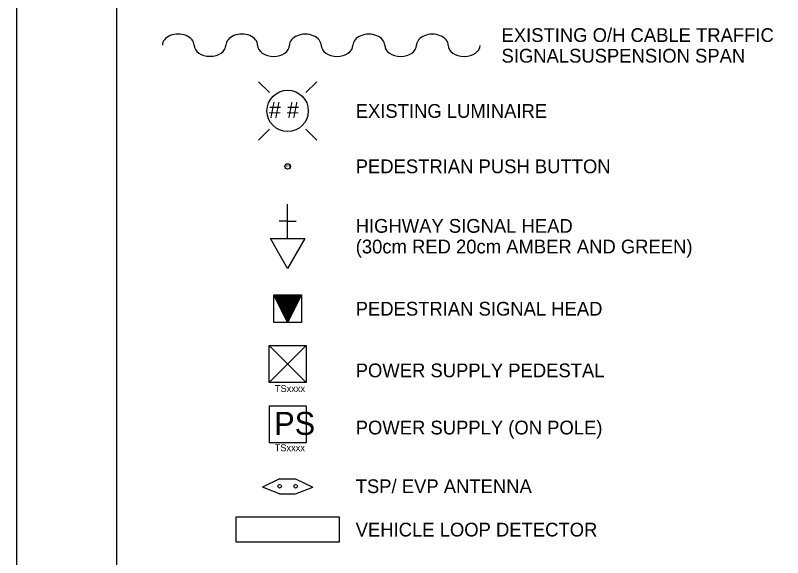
# Model space of a CAD drawing. Extents: x 595568 to 603392, y 4837996 to 4846579.
# Drawn here: x 603056.6 to 603080.76, y 4846502.21 to 4846519.3 of the extents above; entities that cross this region are included whole.
import ezdxf

# ---------------------------------------------------------------- set-up
doc = ezdxf.new("R2010")
doc.units = 0
for name, color, linetype in [('-PRINT HALFSIZE', 7, 'Continuous'), ('ENG_BORDER', 7, 'Continuous'), ('TCS_LEGEND', 7, 'Continuous'), ('TCS_LOOP', 7, 'Continuous'), ('TCS_LUMINAIRE-EXIST', 7, 'Continuous'), ('TCS_POWER', 7, 'Continuous'), ('TCS_PUSHBUTTON', 7, 'Continuous'), ('TCS_SIGNALHEAD', 7, 'Continuous'), ('TCS_SPAN-EXIST', 7, 'Continuous'), ('TCS_TSP-EVP', 7, 'Continuous')]:
    doc.layers.add(name, color=color, linetype=linetype)

msp = doc.modelspace()

# ---------------------------------------------------------------- linework, layer by layer
at = {"layer": '-PRINT HALFSIZE'}
msp.add_lwpolyline([(603056.659, 4846536.385), (603261.877, 4846536.304), (603261.821, 4846396.201), (603056.604, 4846396.282)], close=True, dxfattribs=at)
at = {"layer": 'ENG_BORDER'}
msp.add_lwpolyline([(603059.791, 4846533.885), (603059.791, 4846399.391)], dxfattribs=at)
at = {"layer": 'TCS_LOOP'}
msp.add_lwpolyline([(603063.549, 4846502.701), (603066.803, 4846502.701), (603066.803, 4846503.481), (603063.549, 4846503.481)], close=True, dxfattribs=at)
at = {"layer": 'TCS_LUMINAIRE-EXIST'}
for p, q in [((603064.601, 4846516.86), (603064.256, 4846517.205)), ((603065.751, 4846516.86), (603066.096, 4846517.205)), ((603064.601, 4846515.71), (603064.256, 4846515.365)), ((603065.751, 4846515.71), (603066.096, 4846515.365))]:
    msp.add_line(p, q, dxfattribs=at)
msp.add_circle((603065.176, 4846516.285), 0.651, dxfattribs=at)
at = {"layer": 'TCS_POWER'}
for p, q in [((603064.59, 4846508.897), (603065.762, 4846508.897)), ((603064.59, 4846507.726), (603064.59, 4846508.897)), ((603064.59, 4846508.897), (603065.762, 4846507.726)), ((603064.59, 4846507.726), (603065.762, 4846508.897)), ((603065.762, 4846508.897), (603065.762, 4846507.726)), ((603065.762, 4846507.726), (603064.59, 4846507.726)), ((603064.598, 4846506.995), (603064.598, 4846505.826)), ((603064.598, 4846506.995), (603065.754, 4846506.995)), ((603065.754, 4846506.995), (603065.754, 4846505.826)), ((603065.754, 4846505.826), (603064.598, 4846505.826))]:
    msp.add_line(p, q, dxfattribs=at)
at = {"layer": 'TCS_PUSHBUTTON'}
msp.add_circle((603065.176, 4846514.534), 0.0867, dxfattribs=at)
at = {"layer": 'TCS_SIGNALHEAD'}
for p, q in [((603065.176, 4846512.263), (603065.176, 4846513.351)), ((603065.176, 4846512.807), (603064.904, 4846512.807)), ((603065.176, 4846512.807), (603065.448, 4846512.807)), ((603065.176, 4846511.321), (603064.632, 4846512.263)), ((603064.632, 4846512.263), (603065.72, 4846512.263)), ((603065.72, 4846512.263), (603065.176, 4846511.321)), ((603064.742, 4846509.617), (603064.742, 4846510.484)), ((603064.745, 4846510.478), (603064.752, 4846510.484)), ((603064.752, 4846510.464), (603064.772, 4846510.484)), ((603064.759, 4846510.451), (603064.793, 4846510.484)), ((603064.766, 4846510.437), (603064.813, 4846510.484)), ((603064.773, 4846510.423), (603064.834, 4846510.484)), ((603064.78, 4846510.41), (603064.854, 4846510.484)), ((603064.786, 4846510.396), (603064.875, 4846510.484)), ((603064.793, 4846510.383), (603064.895, 4846510.484)), ((603064.8, 4846510.369), (603064.916, 4846510.484)), ((603064.807, 4846510.355), (603064.936, 4846510.484)), ((603064.814, 4846510.342), (603064.956, 4846510.484)), ((603064.82, 4846510.328), (603064.977, 4846510.484)), ((603064.827, 4846510.314), (603064.997, 4846510.484)), ((603064.834, 4846510.301), (603065.018, 4846510.484)), ((603064.841, 4846510.287), (603065.038, 4846510.484)), ((603064.848, 4846510.274), (603065.059, 4846510.484)), ((603064.855, 4846510.26), (603065.079, 4846510.484)), ((603064.861, 4846510.246), (603065.1, 4846510.484)), ((603064.868, 4846510.233), (603065.12, 4846510.484)), ((603064.875, 4846510.219), (603065.14, 4846510.484)), ((603064.882, 4846510.205), (603065.161, 4846510.484)), ((603064.889, 4846510.192), (603065.181, 4846510.484)), ((603064.895, 4846510.178), (603065.202, 4846510.484)), ((603064.902, 4846510.164), (603065.222, 4846510.484)), ((603064.909, 4846510.151), (603065.243, 4846510.484)), ((603064.916, 4846510.137), (603065.263, 4846510.484)), ((603064.923, 4846510.124), (603065.284, 4846510.484)), ((603064.93, 4846510.11), (603065.304, 4846510.484)), ((603064.936, 4846510.096), (603065.324, 4846510.484)), ((603064.943, 4846510.083), (603065.345, 4846510.484)), ((603064.95, 4846510.069), (603065.365, 4846510.484)), ((603064.957, 4846510.055), (603065.386, 4846510.484)), ((603064.964, 4846510.042), (603065.406, 4846510.484)), ((603064.97, 4846510.028), (603065.427, 4846510.484)), ((603064.977, 4846510.015), (603065.447, 4846510.484)), ((603064.984, 4846510.001), (603065.468, 4846510.484)), ((603064.991, 4846509.987), (603065.488, 4846510.484)), ((603064.998, 4846509.974), (603065.508, 4846510.484)), ((603065.004, 4846509.96), (603065.529, 4846510.484)), ((603065.011, 4846509.946), (603065.549, 4846510.484)), ((603065.018, 4846509.933), (603065.57, 4846510.484)), ((603065.025, 4846509.919), (603065.59, 4846510.484)), ((603065.032, 4846509.905), (603065.609, 4846510.483)), ((603065.039, 4846509.892), (603065.588, 4846510.442)), ((603065.045, 4846509.878), (603065.568, 4846510.401)), ((603065.052, 4846509.865), (603065.547, 4846510.36)), ((603065.059, 4846509.851), (603065.527, 4846510.319)), ((603065.066, 4846509.837), (603065.507, 4846510.278)), ((603065.61, 4846510.484), (603065.61, 4846509.617)), ((603065.073, 4846509.824), (603065.486, 4846510.237)), ((603065.079, 4846509.81), (603065.466, 4846510.196)), ((603065.086, 4846509.796), (603065.445, 4846510.155)), ((603065.093, 4846509.783), (603065.425, 4846510.115)), ((603065.1, 4846509.769), (603065.404, 4846510.074)), ((603065.107, 4846509.756), (603065.384, 4846510.033)), ((603065.114, 4846509.742), (603065.363, 4846509.992)), ((603065.12, 4846509.728), (603065.343, 4846509.951)), ((603065.127, 4846509.715), (603065.323, 4846509.91)), ((603065.134, 4846509.701), (603065.302, 4846509.869)), ((603065.141, 4846509.687), (603065.282, 4846509.828)), ((603065.61, 4846509.617), (603064.742, 4846509.617)), ((603065.148, 4846509.674), (603065.261, 4846509.787)), ((603065.154, 4846509.66), (603065.241, 4846509.746)), ((603065.161, 4846509.646), (603065.22, 4846509.706)), ((603065.168, 4846509.633), (603065.2, 4846509.665)), ((603065.175, 4846509.619), (603065.179, 4846509.624))]:
    msp.add_line(p, q, dxfattribs=at)
for points in [[(603064.632, 4846512.263), (603065.72, 4846512.263), (603065.176, 4846511.321), (603065.176, 4846511.321)], [(603064.742, 4846510.484), (603065.61, 4846510.484), (603065.176, 4846509.617), (603065.176, 4846509.617)]]:
    msp.add_lwpolyline(points, close=True, dxfattribs=at)
at = {"layer": 'TCS_SPAN-EXIST'}
for centre, start_param, end_param in [((603061.732, 4846518.354), 0, 3.141593), ((603063.732, 4846518.353), 0, 3.141593), ((603065.732, 4846518.352), 6.283185, 9.424778), ((603067.732, 4846518.352), 6.283185, 9.424778), ((603069.732, 4846518.351), 0, 3.141593), ((603062.732, 4846518.354), 3.141593, 6.283185), ((603064.732, 4846518.353), 3.141593, 6.283185), ((603066.732, 4846518.352), 3.141593, 6.283185), ((603068.732, 4846518.351), 3.141593, 6.283185), ((603070.732, 4846518.35), 3.141593, 6.283185)]:
    msp.add_ellipse(centre, major_axis=(0.5, 0), ratio=0.7, start_param=start_param, end_param=end_param, dxfattribs=at)
at = {"layer": 'TCS_TSP-EVP'}
for p, q in [((603064.924, 4846504.692), (603064.382, 4846504.428)), ((603064.924, 4846504.692), (603065.176, 4846504.692)), ((603065.176, 4846504.692), (603065.428, 4846504.692)), ((603065.428, 4846504.692), (603065.97, 4846504.428)), ((603064.924, 4846504.223), (603064.382, 4846504.428)), ((603065.428, 4846504.223), (603065.97, 4846504.428)), ((603064.924, 4846504.223), (603065.428, 4846504.223))]:
    msp.add_line(p, q, dxfattribs=at)
for centre in [(603064.924, 4846504.457), (603065.428, 4846504.457)]:
    msp.add_circle(centre, 0.0578, dxfattribs=at)

# ---------------------------------------------------------------- texts
at = {"layer": 'TCS_LEGEND'}
for s, p in [('EXISTING O/H CABLE TRAFFIC', (603071.908, 4846518.457)), ('SIGNALSUSPENSION SPAN', (603071.908, 4846517.806)), ('EXISTING LUMINAIRE', (603067.318, 4846516.066)), ('PEDESTRIAN PUSH BUTTON', (603067.318, 4846514.321)), ('HIGHWAY SIGNAL HEAD ', (603067.318, 4846512.444)), ('(30cm RED 20cm AMBER AND GREEN)', (603067.318, 4846511.794)), ('PEDESTRIAN SIGNAL HEAD', (603067.318, 4846509.834)), ('POWER SUPPLY PEDESTAL', (603067.318, 4846507.891)), ('POWER SUPPLY (ON POLE)', (603067.318, 4846506.09)), ('TSP/ EVP ANTENNA', (603067.318, 4846504.241)), ('VEHICLE LOOP DETECTOR', (603067.318, 4846502.874))]:
    msp.add_text(s, height=0.43374, dxfattribs=at).set_placement(p)
at = {"layer": 'TCS_LUMINAIRE-EXIST'}
msp.add_text('# #', height=0.506, dxfattribs=at).set_placement((603064.588, 4846516.059))
at = {"layer": 'TCS_POWER'}
for s, height, p in [('TSxxxx', 0.2169, (603064.774, 4846507.428)), ('PS', 0.7229, (603064.752, 4846506.077)), ('TSxxxx', 0.2169, (603064.769, 4846505.561))]:
    msp.add_text(s, height=height, dxfattribs=at).set_placement(p)
at = {"layer": 'TCS_PUSHBUTTON'}
msp.add_text('PB', height=0.0906, dxfattribs=at).set_placement((603065.124, 4846514.493))

doc.saveas('drawing.dxf')
